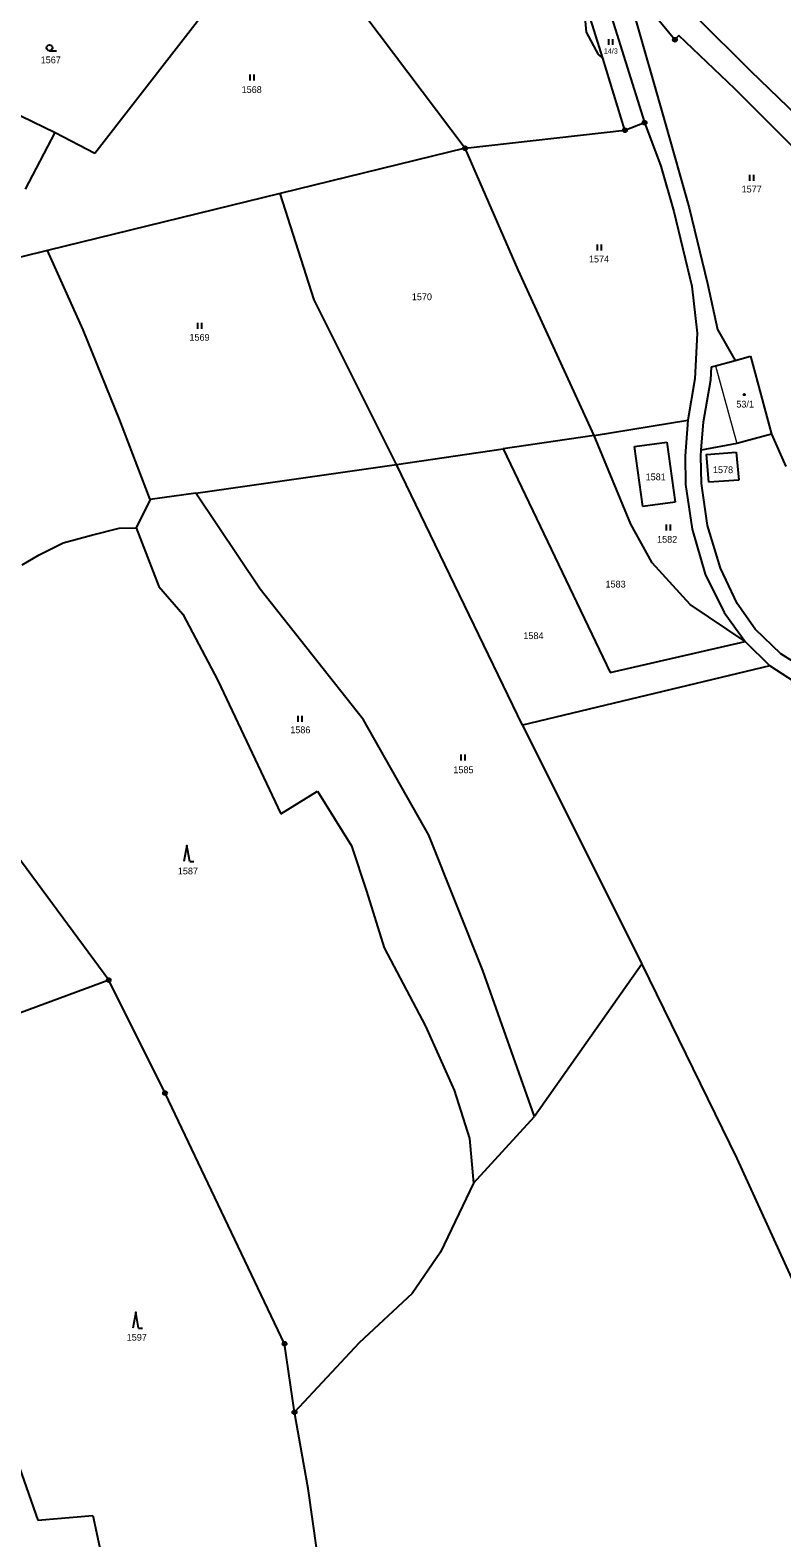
# Model space of a CAD drawing. Extents: x -601131 to -597152, y -1058536 to -1055911.
# Drawn here: x -599584.4 to -599395.7, y -1057934.2 to -1057555.3 of the extents above; entities that cross this region are included whole.
import ezdxf
from ezdxf.enums import TextEntityAlignment as Align

# ---------------------------------------------------------------- set-up
doc = ezdxf.new("R2010")
doc.units = 0
doc.header["$LTSCALE"] = 0.68
for name, color, linetype, lineweight in [('1', 7, 'Continuous', 25), ('3', 7, 'Continuous', 25), ('4', 7, 'Continuous', 13), ('5', 7, 'Continuous', 25), ('8', 7, 'Continuous', 25)]:
    doc.layers.add(name, color=color, linetype=linetype, lineweight=lineweight)
doc.layers.add('2', color=7, linetype='Continuous')

msp = doc.modelspace()

# ---------------------------------------------------------------- linework, layer by layer
at = {"layer": '1'}
for p, q in [((-599568.17, -1057586.29), (-599520.55, -1057524.78)), ((-599520.55, -1057524.78), (-599475.21, -1057585.02)), ((-599439.72, -1057548.06), (-599430.15, -1057578.59)), ((-599445.3, -1057550.3), (-599444.79, -1057555.84)), ((-599440.66, -1057562.39), (-599444.61, -1057549.59)), ((-599433.31, -1057549.41), (-599425.07, -1057578.4)), ((-599422.52, -1057557.74), (-599430.08, -1057548.68)), ((-599403.43, -1057565.64), (-599417.11, -1057552.04)), ((-599444.79, -1057555.84), (-599441.82, -1057561.47)), ((-599421.53, -1057556.67), (-599422.52, -1057557.74)), ((-599407.5, -1057570.06), (-599421.53, -1057556.67)), ((-599441.82, -1057561.47), (-599440.66, -1057562.39)), ((-599435.07, -1057580.49), (-599440.66, -1057562.39)), ((-599386.72, -1057581.85), (-599403.43, -1057565.64)), ((-599391.04, -1057586.5), (-599407.5, -1057570.06)), ((-599592.57, -1057574.09), (-599578.13, -1057581.04)), ((-599435.07, -1057580.49), (-599430.15, -1057578.59)), ((-599430.15, -1057578.59), (-599426.07, -1057589.53)), ((-599425.07, -1057578.4), (-599418.93, -1057600)), ((-599585.58, -1057595.34), (-599578.13, -1057581.04)), ((-599578.13, -1057581.04), (-599568.17, -1057586.29)), ((-599475.21, -1057585.02), (-599435.07, -1057580.49)), ((-599475.21, -1057585.02), (-599521.65, -1057596.41)), ((-599461.87, -1057615.53), (-599475.21, -1057585.02)), ((-599426.07, -1057589.53), (-599422.83, -1057600.94)), ((-599521.65, -1057596.41), (-599580.09, -1057610.74)), ((-599513.13, -1057623.1), (-599521.65, -1057596.41)), ((-599422.83, -1057600.94), (-599418.27, -1057619.7)), ((-599418.93, -1057600), (-599414.33, -1057619.02)), ((-599580.09, -1057610.74), (-599595.83, -1057614.6)), ((-599571.12, -1057630.65), (-599580.09, -1057610.74)), ((-599442.82, -1057657.18), (-599461.87, -1057615.53)), ((-599418.27, -1057619.7), (-599416.96, -1057631.47)), ((-599414.33, -1057619.02), (-599411.83, -1057630.55)), ((-599492.41, -1057664.51), (-599513.13, -1057623.1)), ((-599561.88, -1057653.38), (-599571.12, -1057630.65)), ((-599416.96, -1057631.47), (-599417.48, -1057642.96)), ((-599411.83, -1057630.55), (-599407.4, -1057638.34)), ((-599412.3, -1057639.68), (-599407.4, -1057638.34)), ((-599407.4, -1057638.34), (-599403.56, -1057637.28)), ((-599403.56, -1057637.28), (-599398.23, -1057656.83)), ((-599417.48, -1057642.96), (-599419.31, -1057653.35)), ((-599415.34, -1057653.77), (-599413.48, -1057643.19)), ((-599413.48, -1057643.19), (-599413.34, -1057639.96)), ((-599413.34, -1057639.96), (-599412.3, -1057639.68)), ((-599554.27, -1057673.28), (-599561.88, -1057653.38)), ((-599442.82, -1057657.18), (-599419.31, -1057653.35)), ((-599419.31, -1057653.35), (-599419.97, -1057662.34)), ((-599415.91, -1057660.92), (-599415.34, -1057653.77)), ((-599442.82, -1057657.18), (-599465.65, -1057660.55)), ((-599433.57, -1057679.44), (-599442.82, -1057657.18)), ((-599398.23, -1057656.83), (-599407, -1057659.2)), ((-599398.23, -1057656.83), (-599394.65, -1057664.97)), ((-599492.41, -1057664.51), (-599465.65, -1057660.55)), ((-599465.65, -1057660.55), (-599438.74, -1057716.71)), ((-599432.67, -1057660), (-599424.52, -1057658.88)), ((-599430.58, -1057675.06), (-599432.67, -1057660)), ((-599424.52, -1057658.88), (-599422.42, -1057673.96)), ((-599416.03, -1057662.37), (-599415.91, -1057660.92)), ((-599407, -1057659.2), (-599415.91, -1057660.92)), ((-599407.15, -1057661.4), (-599406.5, -1057668.38)), ((-599542.78, -1057671.65), (-599492.41, -1057664.51)), ((-599460.77, -1057730), (-599492.41, -1057664.51)), ((-599419.97, -1057662.34), (-599419.83, -1057669.51)), ((-599415.84, -1057669.29), (-599416.03, -1057662.37)), ((-599419.83, -1057669.51), (-599418.23, -1057680.69)), ((-599414.33, -1057679.81), (-599415.84, -1057669.29)), ((-599406.5, -1057668.38), (-599413.97, -1057668.91)), ((-599554.27, -1057673.28), (-599557.81, -1057680.43)), ((-599542.78, -1057671.65), (-599554.27, -1057673.28)), ((-599526.66, -1057695.82), (-599542.78, -1057671.65)), ((-599422.42, -1057673.96), (-599430.58, -1057675.06)), ((-599569.02, -1057682.24), (-599562.09, -1057680.52)), ((-599562.09, -1057680.52), (-599557.81, -1057680.43)), ((-599557.81, -1057680.43), (-599552.08, -1057695.13)), ((-599428.22, -1057689.18), (-599433.57, -1057679.44)), ((-599418.23, -1057680.69), (-599414.96, -1057692.02)), ((-599411.11, -1057690.55), (-599414.33, -1057679.81)), ((-599582.14, -1057687.14), (-599576.14, -1057684.18)), ((-599576.14, -1057684.18), (-599569.02, -1057682.24)), ((-599586.38, -1057689.73), (-599582.14, -1057687.14)), ((-599418.69, -1057699.63), (-599428.22, -1057689.18)), ((-599414.96, -1057692.02), (-599410.14, -1057701.69)), ((-599406.85, -1057699.41), (-599411.11, -1057690.55)), ((-599552.08, -1057695.13), (-599546.08, -1057702.12)), ((-599500.74, -1057728.66), (-599526.66, -1057695.82)), ((-599404.89, -1057708.93), (-599418.69, -1057699.63)), ((-599402.36, -1057705.82), (-599406.85, -1057699.41)), ((-599546.08, -1057702.12), (-599537.32, -1057718.79)), ((-599410.14, -1057701.69), (-599404.89, -1057708.93)), ((-599395.94, -1057712.06), (-599402.36, -1057705.82)), ((-599564.68, -1057794.05), (-599626.08, -1057710.77)), ((-599438.74, -1057716.71), (-599404.89, -1057708.93)), ((-599404.89, -1057708.93), (-599398.67, -1057715.05)), ((-599398.67, -1057715.05), (-599460.77, -1057730)), ((-599392.49, -1057719.05), (-599398.67, -1057715.05)), ((-599390.03, -1057715.77), (-599395.94, -1057712.06)), ((-599537.32, -1057718.79), (-599521.48, -1057752.23)), ((-599484.31, -1057757.62), (-599500.74, -1057728.66)), ((-599460.77, -1057730), (-599430.8, -1057790.03)), ((-599521.48, -1057752.23), (-599512.23, -1057746.55)), ((-599512.23, -1057746.55), (-599503.76, -1057760.3)), ((-599503.76, -1057760.3), (-599499.99, -1057771.69)), ((-599470.72, -1057791.64), (-599484.31, -1057757.62)), ((-599499.99, -1057771.69), (-599495.49, -1057785.89)), ((-599495.49, -1057785.89), (-599485.18, -1057805.58)), ((-599430.8, -1057790.03), (-599457.76, -1057828.32)), ((-599430.8, -1057790.03), (-599406.99, -1057838.84)), ((-599564.68, -1057794.05), (-599623.35, -1057815.81)), ((-599550.54, -1057822.44), (-599564.68, -1057794.05)), ((-599457.76, -1057828.32), (-599470.72, -1057791.64)), ((-599485.18, -1057805.58), (-599477.91, -1057821.73)), ((-599520.53, -1057885.42), (-599550.54, -1057822.44)), ((-599477.91, -1057821.73), (-599474.08, -1057833.82)), ((-599473.13, -1057845.04), (-599457.76, -1057828.32)), ((-599474.08, -1057833.82), (-599473.13, -1057845.04)), ((-599406.99, -1057838.84), (-599378.8, -1057900.74)), ((-599473.13, -1057845.04), (-599481.41, -1057862.39)), ((-599481.41, -1057862.39), (-599488.53, -1057872.8)), ((-599488.53, -1057872.8), (-599501.82, -1057885.2)), ((-599518.04, -1057902.62), (-599520.53, -1057885.42)), ((-599501.82, -1057885.2), (-599518.04, -1057902.62)), ((-599514.57, -1057921.81), (-599518.04, -1057902.62)), ((-599587.13, -1057916.58), (-599582.46, -1057929.77)), ((-599512.37, -1057937.8), (-599514.57, -1057921.81)), ((-599582.46, -1057929.77), (-599568.64, -1057928.55)), ((-599568.64, -1057928.55), (-599566.03, -1057941.08))]:
    msp.add_line(p, q, dxfattribs=at)
msp.add_lwpolyline([(-599413.97, -1057668.91), (-599414.63, -1057661.94), (-599407.15, -1057661.4)], dxfattribs=at)
at = {"layer": '3'}
for p, q in [((-599439.121, -1057559.07), (-599439.121, -1057557.57)), ((-599438.12, -1057559.07), (-599438.12, -1057557.57)), ((-599579.563, -1057560.53), (-599577.813, -1057560.53)), ((-599529.151, -1057567.99), (-599529.151, -1057566.49)), ((-599528.15, -1057567.99), (-599528.15, -1057566.49)), ((-599403.721, -1057593.19), (-599403.721, -1057591.69)), ((-599402.72, -1057593.19), (-599402.72, -1057591.69)), ((-599441.991, -1057610.72), (-599441.991, -1057609.22)), ((-599440.99, -1057610.72), (-599440.99, -1057609.22)), ((-599542.331, -1057630.4), (-599542.331, -1057628.9)), ((-599541.33, -1057630.4), (-599541.33, -1057628.9)), ((-599424.631, -1057681.07), (-599424.631, -1057679.57)), ((-599423.63, -1057681.07), (-599423.63, -1057679.57)), ((-599517.091, -1057729.12), (-599517.091, -1057727.62)), ((-599516.09, -1057729.12), (-599516.09, -1057727.62)), ((-599476.181, -1057738.86), (-599476.181, -1057737.36)), ((-599475.18, -1057738.86), (-599475.18, -1057737.36)), ((-599544.31, -1057764.24), (-599543.314, -1057764.24)), ((-599557.17, -1057881.51), (-599556.174, -1057881.51))]:
    msp.add_line(p, q, dxfattribs=at)
for points in [[(-599544.31, -1057764.24), (-599545.06, -1057760.24), (-599545.81, -1057764.24)], [(-599557.17, -1057881.51), (-599557.92, -1057877.51), (-599558.67, -1057881.51)]]:
    msp.add_lwpolyline(points, dxfattribs=at)
msp.add_circle((-599579.5629, -1057559.7798), 0.75, dxfattribs=at)
at = {"layer": '4'}
msp.add_line((-599412.3, -1057639.68), (-599407, -1057659.2), dxfattribs=at)
at = {"layer": '5'}
msp.add_circle((-599405.1268, -1057646.9192), 0.175, dxfattribs=at)
at = {"layer": '8'}
for centre, radius in [((-599422.52, -1057557.7399), 0.5), ((-599422.52, -1057557.7399), 0.0303), ((-599430.15, -1057578.5899), 0.5), ((-599430.15, -1057578.5899), 0.0303), ((-599435.07, -1057580.4899), 0.5), ((-599435.07, -1057580.4899), 0.0303), ((-599475.21, -1057585.0199), 0.5), ((-599475.21, -1057585.0199), 0.0303), ((-599564.68, -1057794.0499), 0.5), ((-599564.68, -1057794.0499), 0.0303), ((-599550.54, -1057822.4399), 0.5), ((-599550.54, -1057822.4399), 0.0303), ((-599520.53, -1057885.4199), 0.5), ((-599520.53, -1057885.4199), 0.0303), ((-599518.04, -1057902.6199), 0.5), ((-599518.04, -1057902.6199), 0.0303)]:
    msp.add_circle(centre, radius, dxfattribs=at)

# ---------------------------------------------------------------- texts
at = {"layer": '2'}
for s, height, p in [('1567', 1.7, (-599579.24, -1057563.662)), ('14/3', 1.3, (-599438.609, -1057561.224)), ('1568', 1.7, (-599528.79, -1057571.122)), ('1577', 1.7, (-599403.25, -1057596.132)), ('1574', 1.7, (-599441.58, -1057613.712)), ('1570', 1.7, (-599486.05, -1057623.192)), ('1569', 1.7, (-599541.89, -1057633.382)), ('53/1', 1.7, (-599404.889, -1057650.172)), ('1578', 1.7, (-599410.44, -1057666.652)), ('1581', 1.7, (-599427.35, -1057668.442)), ('1582', 1.7, (-599424.47, -1057684.132)), ('1583', 1.7, (-599437.42, -1057695.392)), ('1584', 1.7, (-599458.05, -1057708.352)), ('1586', 1.7, (-599516.58, -1057732.002)), ('1585', 1.7, (-599475.62, -1057742.042)), ('1587', 1.7, (-599544.8, -1057767.472)), ('1597', 1.7, (-599557.64, -1057884.642))]:
    msp.add_text(s, height=height, dxfattribs=at).set_placement(p, align=Align.CENTER)

doc.saveas('drawing.dxf')
